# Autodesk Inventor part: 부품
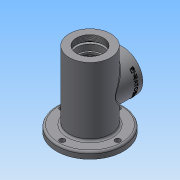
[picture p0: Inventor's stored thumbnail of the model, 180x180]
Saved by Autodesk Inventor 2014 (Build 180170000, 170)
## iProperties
Created: 2016-08
Part Number: 부품
Material: 일반
Document SubType Name: Modeling
Designer: NET
Density: 1 g/cm^3
Appearance: 기본값
Author: NET
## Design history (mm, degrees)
sketch "스케치1"
  geometry: C1 r 31 at (0, 0); 1 further point
  constraints: 1 centre point, 1 coincident
  dimensions: "d0" = 62 diameter of C1
extrude "돌출1" new body sketch "스케치1" stored distance "d1" = 115; taper "d2" = 0 deg
node "작업 평면1"
sketch "스케치2"
  geometry: L1 (31, -57.5)-(31, 57.5) reference; L2 (-31, -57.5)-(-31, 57.5) reference; L3 (-31, -57.5)-(31, -57.5) reference; L4 (31, 57.5)-(-31, 57.5) reference; L5 (0, 57.5)-(0, -57.5); L6 (21, -57.5)-(16.711, -45.491); L7 (13.886, -43.5)-(12.904, -43.5); L8 (12.904, -43.5)-(12.5, -42.8); L9 (12.5, -42.8)-(12.5, -35.8); L10 (12.2, -35.5)-(10, -35.5); L11 (10, -35.5)-(10, -32.8); L12 (10, -32.8)-(13.5, -32.8); L13 (16.5, -29.8)-(16.5, -27.8); L14 (16.5, -27.8)-(17.2, -27.8); L15 (17.5, -27.5)-(17.5, -17.5); L16 (17.5, -17.5)-(23, -17.5); L17 (26, -14.5)-(26, 17.5); L18 (23, 20.5)-(17.5, 20.5); L19 (17.5, 20.5)-(17.5, 31.5); L20 (17.5, 31.5)-(18.5, 31.5); L21 (18.5, 31.5)-(18.5, 33.25); L22 (18.5, 33.25)-(17.5, 33.25); L23 (17.5, 33.25)-(17.5, 36.5); L24 (17.5, 36.5)-(20, 36.5); L25 (20, 36.5)-(20, 45.5); L26 (20, 45.5)-(24, 45.5); L27 (24, 48.5)-(0, 48.5); L28 (24, 48.5)-(24, 45.5); L29 (0, 48.5)-(0, -57.5); L30 (21, -57.5)-(0, -57.5); A1 r 3 centre (13.886, -46.5) between (16.711, -45.491) and (13.886, -43.5); A2 r 3 centre (13.5, -29.8) between (13.5, -32.8) and (16.5, -29.8); A3 r 3 centre (23, -14.5) between (23, -17.5) and (26, -14.5); A4 r 3 centre (23, 17.5) between (26, 17.5) and (23, 20.5); A5 r 0.3 centre (12.2, -35.8) between (12.5, -35.8) and (12.2, -35.5); A6 r 0.3 centre (17.2, -27.5) between (17.2, -27.8) and (17.5, -27.5); 8 further points
  constraints: 52 end point, 14 point on line, 13 perpendicular, 12 point on circle, 12 tangent, 8 parallel, 6 centre point, 3 equal radius, 3 midpoint, 2 collinear
  dimensions: "d4" = 42 diameter of L6.start L5; "d5" = 32 diameter of point (16, -43.5) L5; "d6" = 14 vertical distance of L6.start point (16, -43.5); "d7" = 30 deg angle of L9 L8; "d8" = 0.7 vertical distance of L7.end L8.end; "d9" = 7.3 distance of L8.end point (12.5, -35.5); "d10" = 2.7 distance of L10.end L11.end; "d11" = 25 diameter of L9 L5; "d12" = 20 diameter of L11 L5; "d13" = 33 diameter of L13 L5; "d14" = 35 diameter of L15 L5; "d15" = 52 diameter of L17 L5; "d17" = 38 distance between parallel lines of L18 L16; "d18" = 3 distance of L27.start L26.end; "d19" = 12 distance between parallel lines of L4 L26; "d20" = 48 diameter of L28 L5; "d21" = 40 diameter of L25 L5; "d23" = 35 diameter of L23 L5; "d24" = 35 diameter of L19 L5; "d25" = 21 distance between parallel lines of L4 L24; "d26" = 37 diameter of L21 L5; "d27" = 1.75 distance of L20.end L21.end; "d28" = 26 distance between parallel lines of L4 L20; "d30" = 56 distance from line of L4 point (26, 1.5); "d32" = 3 radius of A1; "d33" = 0.3 radius of A5; "d90" = 0.3 radius of A6; "d91" = 5 distance from line of L11.end L14
revolve "회전1" sketch "스케치2" stored, may be unused: angle "d31" = 90 deg
hole "구멍1" diameter "d36" = 40.376; stored, may be unused: countersink angle "d40" = 90 deg, drill point angle "d42" = 118 deg; dims "d34" = 10, "d35" = 10, "d37" = 9, "d38" = 4, "d39" = 2, "d41" = 9
sketch "스케치3"
  geometry: L1 (31, 57.5)-(-31, 57.5) reference; C1 r 30 at (0, 1.5); 1 further point
  constraints: 1 centre point, 1 vertical alignment
  dimensions: "d43" = 60 diameter of C1; "d44" = 56 distance from line of L1 C1.centre
extrude "돌출2" join sketch "스케치3" stored distance "d45" = 115; taper "d46" = 0 deg
hole "구멍2" diameter "d49" = 38; stored, may be unused: countersink angle "d53" = 90 deg, drill point angle "d55" = 118 deg; dims "d47" = 10, "d48" = 10, "d50" = 38, "d51" = 4, "d52" = 2, "d54" = 9
chamfer "모따기1" distance "d56" = 1; stored, may be unused: second distance "d57" = 2, angle "d58" = 45 deg
node "작업 평면2"
sketch "스케치4"
  geometry: C1 r 50 at (0, 0); C2 r 31 at (0, 0) reference; C3 r 31 at (0, 0); 1 further point
  constraints: 2 centre point, 2 coincident, 1 concentric
  dimensions: "d60" = 100 diameter of C1
extrude "돌출3" join sketch "스케치4" distance "d61" = 10; taper "d62" = 0 deg
sketch "스케치5"
  geometry: C1 r 31 at (0, 0) reference; C2 r 4 at (0, 41.5)
  constraints: 1 centre point, 1 vertical alignment
  dimensions: "d63" = 8 diameter of C2; "d64" = 41.5 distance of C1.centre C2.centre
extrude "돌출4" cut sketch "스케치5" stored distance "d65" = 10; taper "d66" = 0 deg
fillet "모깎기1" dims "d70" = 3
sketch "스케치6"
  geometry: C1 r 30 at (0, 0) reference; 2 further points
  constraints: 1 horizontal alignment
  dimensions: "d71" = 24 distance of point (-24, 0) C1.centre
hole "구멍3" sketch "스케치6" at (-24, 0) diameter "d72" = 3.242; stored, may be unused: countersink angle "d76" = 90 deg, drill point angle "d78" = 118 deg; dims "d73" = 8, "d74" = 4, "d75" = 2, "d77" = 10
chamfer "모따기2" distance "d82" = 1; stored, may be unused: second distance "d83" = 2, angle "d84" = 45 deg
node "작업 평면3"
sketch "스케치7"
  geometry: L1 (49, 31.5)-(49, -28.5) reference; L2 (31, 57.5)-(-31, 57.5) reference; 2 further points
  constraints: 1 other
  dimensions: "d86" = 10 distance from line of L1 point (39, 1.5); "d87" = 56 distance from line of L2 point (39, 1.5)
feature "엠보싱1" sketch "스케치7" dims "d88" = 0.5, "d89" = 0
node "솔리드1"
pattern_circular "원형 패턴1" dims angle "d68" = 360 deg
pattern_circular "원형 패턴2" dims angle "d80" = 360 deg
other parameters: "d3" = 49, "d59" = -44.5
